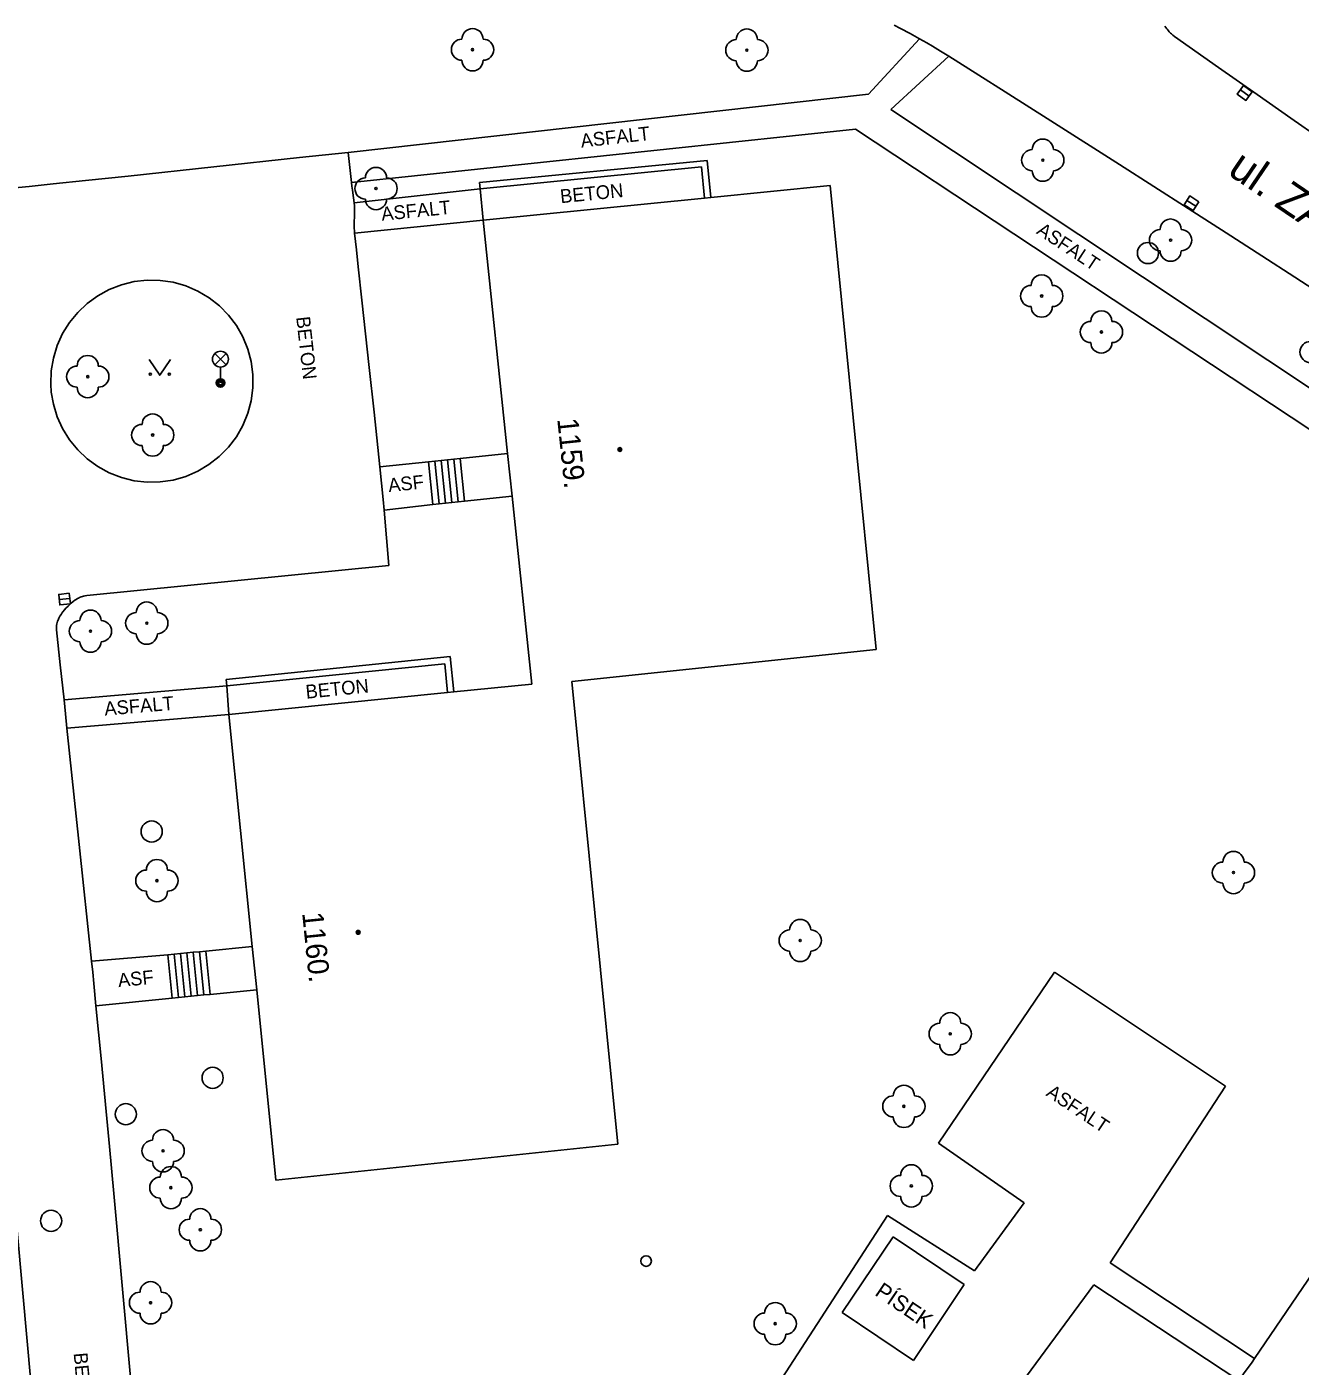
# Model space of a CAD drawing. Extents: x -539515 to -538098, y -1182060 to -1180157.
# Drawn here: x -538776.9 to -538716.8, y -1181163.7 to -1181100.4 of the extents above; entities that cross this region are included whole.
import ezdxf

# ---------------------------------------------------------------- set-up
doc = ezdxf.new("R2010")
doc.units = 0
for name, color, linetype in [('Vrstva 1', 7, 'Continuous'), ('Vrstva 13', 7, 'Continuous'), ('Vrstva 22', 7, 'Continuous'), ('Vrstva 27', 7, 'Continuous'), ('Vrstva 31', 7, 'Continuous'), ('Vrstva 33', 7, 'Continuous'), ('Vrstva 36', 7, 'Continuous'), ('Vrstva 39', 7, 'Continuous'), ('Vrstva 40', 7, 'Continuous'), ('Vrstva 41', 7, 'Continuous'), ('Vrstva 47', 7, 'Continuous'), ('Vrstva 49', 7, 'Continuous'), ('Vrstva 68', 7, 'Continuous'), ('Vrstva 88', 7, 'Continuous')]:
    doc.layers.add(name, color=color, linetype=linetype)

msp = doc.modelspace()

# ---------------------------------------------------------------- linework, layer by layer
at = {"layer": 'Vrstva 1'}
for p, q in [((-538744.596, -1181108.473), (-538738.97, -1181107.91)), ((-538738.97, -1181107.91), (-538736.79, -1181129.84)), ((-538755.36, -1181109.55), (-538744.894, -1181108.502)), ((-538744.894, -1181108.502), (-538744.596, -1181108.473)), ((-538754.203, -1181120.577), (-538755.36, -1181109.55)), ((-538753.992, -1181122.588), (-538754.203, -1181120.577)), ((-538753.06, -1181131.47), (-538753.992, -1181122.588)), ((-538751.167, -1181131.348), (-538736.79, -1181129.84)), ((-538756.741, -1181131.84), (-538753.06, -1181131.47)), ((-538751.167, -1181131.348), (-538748.993, -1181153.212)), ((-538767.37, -1181132.91), (-538757.039, -1181131.87)), ((-538757.039, -1181131.87), (-538756.741, -1181131.84)), ((-538766.264, -1181143.868), (-538767.37, -1181132.91)), ((-538766.058, -1181145.914), (-538766.264, -1181143.868)), ((-538765.15, -1181154.91), (-538766.058, -1181145.914)), ((-538748.993, -1181153.212), (-538765.15, -1181154.91))]:
    msp.add_line(p, q, dxfattribs=at)
at = {"layer": 'Vrstva 13'}
for p, q in [((-538737.16, -1181103.59), (-538734.75, -1181100.97)), ((-538733.36, -1181101.8), (-538736.1, -1181104.32)), ((-538761.73, -1181106.34), (-538737.16, -1181103.59)), ((-538736.1, -1181104.32), (-538692.02, -1181133.63)), ((-538761.58, -1181107.76), (-538737.76, -1181105.24)), ((-538692.58, -1181135.14), (-538737.76, -1181105.24)), ((-538761.45, -1181108.73), (-538755.5, -1181108.068)), ((-538755.5, -1181108.068), (-538755.36, -1181109.55)), ((-538755.36, -1181109.55), (-538761.43, -1181110.16)), ((-538757.642, -1181120.937), (-538757.431, -1181122.948)), ((-538757.344, -1181120.906), (-538757.133, -1181122.917)), ((-538757.045, -1181120.875), (-538756.834, -1181122.886)), ((-538756.747, -1181120.843), (-538756.536, -1181122.854)), ((-538756.449, -1181120.812), (-538756.238, -1181122.823)), ((-538757.941, -1181120.969), (-538760.24, -1181121.21)), ((-538757.941, -1181120.969), (-538757.73, -1181122.98)), ((-538757.73, -1181122.98), (-538760.04, -1181123.25)), ((-538775.16, -1181132.22), (-538767.47, -1181131.55)), ((-538767.47, -1181131.55), (-538767.37, -1181132.91)), ((-538767.37, -1181132.91), (-538775.02, -1181133.55)), ((-538770.25, -1181144.27), (-538773.86, -1181144.56)), ((-538770.044, -1181146.316), (-538770.25, -1181144.27)), ((-538769.745, -1181146.285), (-538769.951, -1181144.239)), ((-538769.447, -1181146.255), (-538769.653, -1181144.209)), ((-538769.148, -1181146.225), (-538769.354, -1181144.179)), ((-538768.85, -1181146.195), (-538769.056, -1181144.149)), ((-538768.551, -1181146.165), (-538768.757, -1181144.119)), ((-538768.253, -1181146.135), (-538768.459, -1181144.089)), ((-538728.37, -1181145.09), (-538733.84, -1181153.17)), ((-538720.29, -1181150.47), (-538728.37, -1181145.09)), ((-538770.044, -1181146.316), (-538773.65, -1181146.68)), ((-538725.74, -1181158.82), (-538720.29, -1181150.47)), ((-538733.84, -1181153.17), (-538729.8, -1181155.99)), ((-538729.8, -1181155.99), (-538732.15, -1181159.2)), ((-538736.25, -1181156.58), (-538742.75, -1181166.61)), ((-538732.15, -1181159.2), (-538736.25, -1181156.58)), ((-538718.91, -1181163.34), (-538725.74, -1181158.82)), ((-538735.22, -1181171.66), (-538726.507, -1181159.859)), ((-538719.66, -1181164.39), (-538726.507, -1181159.859))]:
    msp.add_line(p, q, dxfattribs=at)
for points in [[(-538754.203, -1181120.577), (-538756.449, -1181120.812), (-538756.747, -1181120.843), (-538757.045, -1181120.875), (-538757.344, -1181120.906), (-538757.642, -1181120.937), (-538757.941, -1181120.969)], [(-538753.992, -1181122.588), (-538756.238, -1181122.823), (-538756.536, -1181122.854), (-538756.834, -1181122.886), (-538757.133, -1181122.917), (-538757.431, -1181122.948), (-538757.73, -1181122.98)], [(-538766.264, -1181143.868), (-538768.459, -1181144.089), (-538768.757, -1181144.119), (-538769.056, -1181144.149), (-538769.354, -1181144.179), (-538769.653, -1181144.209), (-538769.951, -1181144.239), (-538770.25, -1181144.27)], [(-538766.058, -1181145.914), (-538768.253, -1181146.135), (-538768.551, -1181146.165), (-538768.85, -1181146.195), (-538769.148, -1181146.225), (-538769.447, -1181146.255), (-538769.745, -1181146.285), (-538770.044, -1181146.316)]]:
    msp.add_lwpolyline(points, dxfattribs=at)
at = {"layer": 'Vrstva 22'}
for centre in [(-538755.86, -1181101.49), (-538742.9, -1181101.51), (-538728.92, -1181106.71), (-538760.42, -1181108.05), (-538722.88, -1181110.49), (-538728.97, -1181113.13), (-538726.15, -1181114.83), (-538774.04, -1181116.94), (-538770.97, -1181119.7), (-538771.25, -1181128.59), (-538773.91, -1181128.97), (-538719.91, -1181140.38), (-538770.77, -1181140.76), (-538740.38, -1181143.59), (-538733.29, -1181148), (-538735.48, -1181151.43), (-538770.48, -1181153.53), (-538735.13, -1181155.19), (-538770.11, -1181155.27), (-538768.72, -1181157.26), (-538771.07, -1181160.71), (-538741.56, -1181161.7)]:
    msp.add_circle(centre, 0.05, dxfattribs=at)
for centre, start, end in [((-538755.86, -1181100.99), 0, 180), ((-538742.9, -1181101.01), 0, 180), ((-538756.36, -1181101.49), 90, 270), ((-538755.36, -1181101.49), 270, 90), ((-538743.4, -1181101.51), 90, 270), ((-538742.4, -1181101.51), 270, 90), ((-538755.86, -1181101.99), 180, 0), ((-538742.9, -1181102.01), 180, 0), ((-538728.92, -1181106.21), 0, 180), ((-538729.42, -1181106.71), 90, 270), ((-538728.42, -1181106.71), 270, 90), ((-538760.92, -1181108.05), 90, 270), ((-538760.42, -1181107.55), 0, 180), ((-538759.92, -1181108.05), 270, 90), ((-538728.92, -1181107.21), 180, 0), ((-538760.42, -1181108.55), 180, 0), ((-538722.88, -1181109.99), 359.99978, 179.99978), ((-538723.38, -1181110.49), 89.99978, 269.99978), ((-538722.38, -1181110.49), 269.99978, 89.99978), ((-538722.88, -1181110.99), 179.99978, 359.99978), ((-538729.47, -1181113.13), 89.99978, 269.99978), ((-538728.97, -1181112.63), 359.99978, 179.99978), ((-538728.47, -1181113.13), 269.99978, 89.99978), ((-538728.97, -1181113.63), 179.99978, 359.99978), ((-538726.15, -1181114.33), 359.99978, 179.99978), ((-538726.65, -1181114.83), 89.99978, 269.99978), ((-538725.65, -1181114.83), 269.99978, 89.99978), ((-538726.15, -1181115.33), 179.99978, 359.99978), ((-538716.27, -1181115.78), 89.99978, 269.99978), ((-538774.54, -1181116.94), 90, 270), ((-538774.04, -1181116.44), 0, 180), ((-538773.54, -1181116.94), 270, 90), ((-538774.04, -1181117.44), 180, 0), ((-538770.97, -1181119.2), 0, 180), ((-538771.47, -1181119.7), 90, 270), ((-538770.47, -1181119.7), 270, 90), ((-538770.97, -1181120.2), 180, 0), ((-538771.25, -1181128.09), 0, 180), ((-538774.41, -1181128.97), 90, 270), ((-538773.91, -1181128.47), 0, 180), ((-538773.41, -1181128.97), 270, 90), ((-538771.75, -1181128.59), 90, 270), ((-538770.75, -1181128.59), 270, 90), ((-538771.25, -1181129.09), 180, 0), ((-538773.91, -1181129.47), 180, 0), ((-538770.77, -1181140.26), 0, 180), ((-538720.41, -1181140.38), 90, 270), ((-538719.91, -1181139.88), 360, 180), ((-538719.41, -1181140.38), 270, 90), ((-538771.27, -1181140.76), 90, 270), ((-538770.27, -1181140.76), 270, 90), ((-538719.91, -1181140.88), 180, 360), ((-538770.77, -1181141.26), 180, 0), ((-538740.88, -1181143.59), 90, 270), ((-538740.38, -1181143.09), 0, 180), ((-538739.88, -1181143.59), 270, 90), ((-538740.38, -1181144.09), 180, 0), ((-538733.79, -1181148), 90, 270), ((-538733.29, -1181147.5), 360, 180), ((-538732.79, -1181148), 270, 90), ((-538733.29, -1181148.5), 180, 360), ((-538735.48, -1181150.93), 0, 180), ((-538735.98, -1181151.43), 90, 270), ((-538734.98, -1181151.43), 270, 90), ((-538735.48, -1181151.93), 180, 0), ((-538770.48, -1181153.03), 0, 180), ((-538770.98, -1181153.53), 90, 270), ((-538769.98, -1181153.53), 270, 90), ((-538770.48, -1181154.03), 180, 0), ((-538770.11, -1181154.77), 0, 180), ((-538735.13, -1181154.69), 0, 180), ((-538770.61, -1181155.27), 90, 270), ((-538769.61, -1181155.27), 270, 90), ((-538735.63, -1181155.19), 90, 270), ((-538734.63, -1181155.19), 270, 90), ((-538770.11, -1181155.77), 180, 0), ((-538735.13, -1181155.69), 180, 0), ((-538768.72, -1181156.76), 0, 180), ((-538769.22, -1181157.26), 90, 270), ((-538768.22, -1181157.26), 270, 90), ((-538768.72, -1181157.76), 180, 0), ((-538771.57, -1181160.71), 90, 270), ((-538771.07, -1181160.21), 0, 180), ((-538770.57, -1181160.71), 270, 90), ((-538741.56, -1181161.2), 0, 180), ((-538771.07, -1181161.21), 180, 0), ((-538742.06, -1181161.7), 90, 270), ((-538741.06, -1181161.7), 270, 90), ((-538741.56, -1181162.2), 180, 0)]:
    msp.add_arc(centre, 0.5, start, end, dxfattribs=at)
at = {"layer": 'Vrstva 27'}
for p, q in [((-538719.175, -1181103.678), (-538719.585, -1181103.39)), ((-538721.687, -1181108.883), (-538722.109, -1181108.613)), ((-538774.885, -1181127.431), (-538775.383, -1181127.481))]:
    msp.add_line(p, q, dxfattribs=at)
for points in [[(-538719.032, -1181103.473), (-538719.441, -1181103.186), (-538719.728, -1181103.595), (-538719.319, -1181103.882)], [(-538721.553, -1181108.672), (-538721.974, -1181108.403), (-538722.243, -1181108.824), (-538721.822, -1181109.093)], [(-538774.91, -1181127.182), (-538775.408, -1181127.232), (-538775.358, -1181127.73), (-538774.86, -1181127.68)]]:
    msp.add_lwpolyline(points, close=True, dxfattribs=at)
for centre in [(-538723.95, -1181111.1), (-538771.02, -1181138.44), (-538768.14, -1181150.08), (-538772.24, -1181151.8), (-538775.77, -1181156.84)]:
    msp.add_circle(centre, 0.5, dxfattribs=at)
at = {"layer": 'Vrstva 31'}
msp.add_circle((-538747.66, -1181158.74), 0.25, dxfattribs=at)
at = {"layer": 'Vrstva 33'}
for p, q in [((-538768.035, -1181116.38), (-538767.505, -1181115.85)), ((-538768.035, -1181115.85), (-538767.505, -1181116.38)), ((-538767.77, -1181116.49), (-538767.77, -1181117.24))]:
    msp.add_line(p, q, dxfattribs=at)
for centre, radius in [((-538767.77, -1181116.115), 0.375), ((-538767.77, -1181117.24), 0.2), ((-538767.77, -1181117.24), 0.145), ((-538767.77, -1181117.24), 0.0876)]:
    msp.add_circle(centre, radius, dxfattribs=at)
at = {"layer": 'Vrstva 36'}
msp.add_lwpolyline([(-538771.134, -1181116.125), (-538770.634, -1181116.875), (-538770.134, -1181116.125)], dxfattribs=at)
for centre in [(-538771.084, -1181116.825), (-538770.185, -1181116.825)]:
    msp.add_circle(centre, 0.05, dxfattribs=at)
at = {"layer": 'Vrstva 39'}
for centre, radius in [((-538748.9, -1181120.386), 0.09), ((-538748.9, -1181120.386), 0.0398), ((-538761.262, -1181143.204), 0.09), ((-538761.262, -1181143.204), 0.0398)]:
    msp.add_circle(centre, radius, dxfattribs=at)
at = {"layer": 'Vrstva 68'}
for p, q in [((-538755.5, -1181108.068), (-538745.041, -1181107.024)), ((-538744.894, -1181108.502), (-538745.041, -1181107.024)), ((-538744.596, -1181108.473), (-538744.77, -1181106.73)), ((-538756.741, -1181131.84), (-538756.91, -1181130.16)), ((-538767.47, -1181131.55), (-538757.175, -1181130.514)), ((-538757.175, -1181130.514), (-538757.039, -1181131.87))]:
    msp.add_line(p, q, dxfattribs=at)
for points in [[(-538744.77, -1181106.73), (-538755.53, -1181107.77)], [(-538755.53, -1181107.77), (-538755.5, -1181108.068)], [(-538756.91, -1181130.16), (-538767.5, -1181131.251)], [(-538767.5, -1181131.251), (-538767.47, -1181131.55)]]:
    msp.add_lwpolyline(points, dxfattribs=at)
at = {"layer": 'Vrstva 88'}
for p, q in [((-538761.73, -1181106.34), (-538764.041, -1181106.586)), ((-538761.655, -1181107.05), (-538761.73, -1181106.34)), ((-538764.041, -1181106.586), (-538772.128, -1181107.463)), ((-538766.955, -1181126.575), (-538759.82, -1181125.86)), ((-538774.09, -1181127.29), (-538766.955, -1181126.575)), ((-538774.44, -1181139.055), (-538775.02, -1181133.55)), ((-538773.86, -1181144.56), (-538774.44, -1181139.055)), ((-538778.41, -1181145.91), (-538776.89, -1181162.7)), ((-538771.997, -1181164.423), (-538772.808, -1181155.55)), ((-538735.987, -1181157.588), (-538738.4, -1181161.17)), ((-538732.63, -1181159.85), (-538735.987, -1181157.588)), ((-538718.91, -1181163.34), (-538715.39, -1181158.17)), ((-538735.03, -1181163.44), (-538732.63, -1181159.85)), ((-538738.4, -1181161.17), (-538735.03, -1181163.44))]:
    msp.add_line(p, q, dxfattribs=at)
for points in [[(-538735.936, -1181100.322), (-538735.638, -1181100.48), (-538735.192, -1181100.722), (-538734.75, -1181100.97), (-538734.399, -1181101.172), (-538734.137, -1181101.326), (-538733.747, -1181101.561), (-538733.36, -1181101.8), (-538731.941, -1181102.691), (-538730.702, -1181103.474), (-538728.536, -1181104.848)], [(-538723.147, -1181100.369), (-538723.101, -1181100.441), (-538723.058, -1181100.502), (-538723.019, -1181100.554), (-538722.947, -1181100.64), (-538722.889, -1181100.7), (-538722.844, -1181100.743), (-538722.774, -1181100.804), (-538722.7, -1181100.86)], [(-538722.7, -1181100.86), (-538720.62, -1181102.329), (-538718.796, -1181103.61), (-538717.197, -1181104.727), (-538715.796, -1181105.702), (-538714.568, -1181106.553)], [(-538728.536, -1181104.848), (-538725.292, -1181106.917), (-538722.05, -1181108.99), (-538720.254, -1181110.141)], [(-538772.128, -1181107.463), (-538774.15, -1181107.678), (-538775.667, -1181107.835), (-538776.805, -1181107.95), (-538778.512, -1181108.118), (-538780.22, -1181108.28), (-538780.752, -1181108.326), (-538781.551, -1181108.389)], [(-538760.742, -1181116.505), (-538761.094, -1181113.333), (-538761.266, -1181111.747), (-538761.349, -1181110.953), (-538761.43, -1181110.16), (-538761.438, -1181110.071), (-538761.445, -1181109.904), (-538761.446, -1181109.757), (-538761.434, -1181109.243), (-538761.432, -1181109.114), (-538761.433, -1181109.018), (-538761.438, -1181108.874), (-538761.45, -1181108.73), (-538761.48, -1181108.487), (-538761.533, -1181108.124), (-538761.558, -1181107.942), (-538761.58, -1181107.76), (-538761.655, -1181107.05)], [(-538720.254, -1181110.141), (-538718.575, -1181111.224), (-538717.006, -1181112.242)], [(-538769.407, -1181112.651), (-538770.002, -1181112.482), (-538770.613, -1181112.391), (-538771.231, -1181112.38), (-538771.845, -1181112.449), (-538772.445, -1181112.596), (-538773.022, -1181112.819), (-538773.564, -1181113.115), (-538774.064, -1181113.479), (-538774.513, -1181113.904), (-538774.903, -1181114.383), (-538775.228, -1181114.909), (-538775.482, -1181115.472), (-538775.662, -1181116.063), (-538775.764, -1181116.673), (-538775.786, -1181117.29), (-538775.76, -1181117.67)], [(-538768.84, -1181112.896), (-538769.407, -1181112.651)], [(-538717.006, -1181112.242), (-538715.538, -1181113.2), (-538714.166, -1181114.102), (-538712.882, -1181114.95), (-538711.68, -1181115.749), (-538710.555, -1181116.5), (-538709.502, -1181117.208)], [(-538768.311, -1181121.098), (-538767.824, -1181120.717), (-538767.391, -1181120.276), (-538767.018, -1181119.783), (-538766.712, -1181119.246), (-538766.478, -1181118.674), (-538766.32, -1181118.077), (-538766.24, -1181117.464), (-538766.24, -1181116.846), (-538766.319, -1181116.233), (-538766.477, -1181115.636), (-538766.711, -1181115.064), (-538767.017, -1181114.527), (-538767.389, -1181114.034), (-538767.822, -1181113.592), (-538768.308, -1181113.211), (-538768.84, -1181112.896)], [(-538759.82, -1181125.86), (-538759.93, -1181124.555), (-538760.04, -1181123.25), (-538760.086, -1181122.74), (-538760.162, -1181121.975), (-538760.24, -1181121.21), (-538760.381, -1181119.828), (-538760.509, -1181118.619), (-538760.742, -1181116.505)], [(-538775.76, -1181117.67), (-538775.662, -1181118.242), (-538775.483, -1181118.833), (-538775.229, -1181119.397), (-538774.904, -1181119.923), (-538774.514, -1181120.402), (-538774.066, -1181120.827), (-538773.566, -1181121.191), (-538773.024, -1181121.487), (-538772.448, -1181121.711), (-538771.848, -1181121.859), (-538771.234, -1181121.928), (-538770.616, -1181121.917), (-538770.004, -1181121.826), (-538769.41, -1181121.657), (-538768.842, -1181121.413), (-538768.311, -1181121.098)], [(-538775.02, -1181133.55), (-538775.09, -1181132.885), (-538775.16, -1181132.22), (-538775.335, -1181130.56), (-538775.51, -1181128.9), (-538775.514, -1181128.775), (-538775.508, -1181128.699), (-538775.497, -1181128.629), (-538775.482, -1181128.564), (-538775.464, -1181128.504), (-538775.443, -1181128.448), (-538775.421, -1181128.397), (-538775.399, -1181128.349), (-538775.35, -1181128.26), (-538775.302, -1181128.183), (-538775.257, -1181128.117), (-538775.214, -1181128.06), (-538775.133, -1181127.962), (-538775.069, -1181127.89), (-538774.967, -1181127.784), (-538774.86, -1181127.68), (-538774.815, -1181127.639), (-538774.731, -1181127.568), (-538774.656, -1181127.512), (-538774.589, -1181127.467), (-538774.531, -1181127.432), (-538774.478, -1181127.404), (-538774.432, -1181127.382), (-538774.35, -1181127.349), (-538774.287, -1181127.328), (-538774.239, -1181127.315), (-538774.165, -1181127.3), (-538774.09, -1181127.29)], [(-538773.753, -1181145.62), (-538773.806, -1181145.09), (-538773.86, -1181144.56)], [(-538772.808, -1181155.55), (-538773.013, -1181153.332), (-538773.169, -1181151.669), (-538773.407, -1181149.174), (-538773.65, -1181146.68), (-538773.753, -1181145.62)], [(-538776.89, -1181162.7), (-538775.509, -1181177.959)], [(-538719.66, -1181164.39), (-538719.568, -1181164.257), (-538719.404, -1181164.028), (-538719.154, -1181163.686), (-538719.031, -1181163.514), (-538718.91, -1181163.34)]]:
    msp.add_lwpolyline(points, dxfattribs=at)

# ---------------------------------------------------------------- texts
at = {"layer": 'Vrstva 40'}
for s, rotation, p in [('ASFALT', 6.38626, (-538750.719, -1181106.118)), ('BETON', 5.71406, (-538751.69, -1181108.746)), ('ASFALT', 5.73863, (-538760.142, -1181109.577)), ('ASFALT', 326.50352, (-538729.257, -1181110.156)), ('BETON', 276.34229, (-538764.192, -1181114.129)), ('ASF', 5.98436, (-538759.813, -1181122.4)), ('BETON', 5.74627, (-538763.714, -1181132.165)), ('ASFALT', 4.78223, (-538773.229, -1181132.96)), ('ASF', 5.76408, (-538772.583, -1181145.798)), ('ASFALT', 326.34267, (-538728.804, -1181150.897)), ('BETON', 275.17289, (-538774.707, -1181163.094))]:
    msp.add_text(s, height=0.65, rotation=rotation, dxfattribs=at).set_placement(p)
at = {"layer": 'Vrstva 41'}
msp.add_text('PÍSEK', height=0.75, rotation=326.02728, dxfattribs=at).set_placement((-538736.899, -1181160.326))
at = {"layer": 'Vrstva 47'}
for s, rotation, p in [('1159.', 275.98996, (-538751.861, -1181118.945)), ('1160.', 275.76216, (-538763.911, -1181142.288))]:
    msp.add_text(s, height=1, rotation=rotation, dxfattribs=at).set_placement(p)
at = {"layer": 'Vrstva 49'}
msp.add_text('ul. ZAHRADNÍ', height=1.5, rotation=325.81104, dxfattribs=at).set_placement((-538720.248, -1181107.342))

doc.saveas('drawing.dxf')
